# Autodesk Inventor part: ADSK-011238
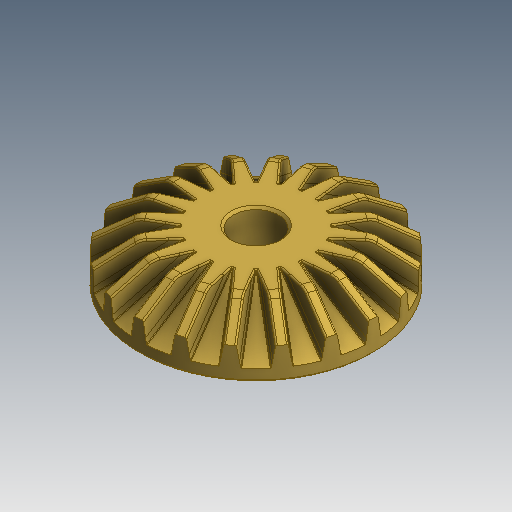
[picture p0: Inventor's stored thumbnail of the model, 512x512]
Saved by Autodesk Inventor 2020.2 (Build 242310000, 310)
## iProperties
Created: 2000-10
Part Number: ADSK-011238
Document SubType Name: Modeling
Designer: wymerj
Material: Générique
Density: 1 g/cm^3
Appearance: Vorgabe
Mass: 62.3454 g
Surface Area: 155.398 cm^2
Volume: 62.3454 cm^3
Control State: 0
Master: False
Checked Out: False
Shininess: 0.0
Length Units: 11269
Angle Units: 11279
Time Units: 11290
Mass Units: 11283
Length Display Precision: 3
Angle Display Precision: 2
Compacted: True
Dimensions: 17,9x80,1x80,1 mm
Mass: 0,062 kg
VLT_Material: Generic
Density: 0.0
Volumn: 0.0
Area: 0.0
PropertySet Name: Model Information
Author: wymerj
Revision Number: -
Title: ADSK-011238
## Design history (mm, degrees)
derived "ADSK-011826.ipt"
  workplane "Work Plane1"
  workaxis "Work Axis1"
  workaxis "Work Axis2"
workaxis "Work Axis3"
node "Solide1"
node "Corps solides"
node "Corps surfaciques"
node "FonctionRepérage2"
sketch "Sketch2"
  geometry: 6 further points; 4 other entities
  constraints: 2 vertical alignment, 1 horizontal alignment, 3 other
feature "DerivedBody::ADSK-011826.ipt"
